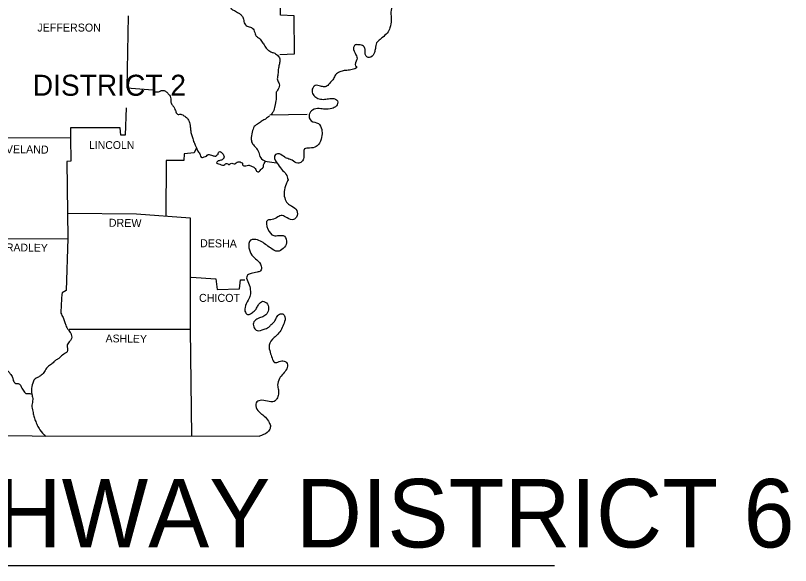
# Model space of a CAD drawing. Extents: x -984 to 3998, y 83 to 2143.
# Drawn here: x 2999.8 to 3407.1, y 1332.5 to 1621.8 of the extents above; entities that cross this region are included whole.
import ezdxf

# ---------------------------------------------------------------- set-up
doc = ezdxf.new("R2010")
doc.units = 0
for name, color, linetype in [('Level 1', 7, 'Continuous'), ('Level 2', 7, 'Continuous'), ('Level 3', 7, 'Continuous')]:
    doc.layers.add(name, color=color, linetype=linetype)

msp = doc.modelspace()

# ---------------------------------------------------------------- linework, layer by layer
at = {"layer": 'Level 1'}
msp.add_line((3133.42, 1569.58), (3152.99, 1569.88), dxfattribs=at)
for points in [[(3138.71, 1601.18), (3146.34, 1601.67), (3146.24, 1621.54), (3139.1, 1622.02), (3139.49, 1660.87), (3133.33, 1661.75), (3133.13, 1687.87), (3216.59, 1688.46)], [(3059.06, 1621.63), (3058.28, 1583.77), (3071.88, 1582.69)], [(3057.99, 1573.3), (3057.4, 1558.92), (3055.15, 1558.92), (3054.76, 1562.73), (3028.73, 1562.73), (3028.73, 1557.25)], [(2993.9, 1557.55), (3028.54, 1557.35)], [(3028.73, 1557.35), (3028.83, 1545.12), (3026.78, 1545.02), (3027.36, 1504.42)], [(3094.87, 1552.17), (3093.7, 1549.52), (3088.51, 1549.04), (3088.22, 1545.51), (3078.93, 1545.51), (3078.83, 1516.26)], [(3027.07, 1517.73), (3063.37, 1517.43), (3091.55, 1515.28)], [(3091.55, 1515.28), (3091.55, 1456.77), (3092.33, 1400.51)], [(2983.14, 1504.32), (3027.36, 1504.42)], [(3027.36, 1504.42), (3026.39, 1477.22), (3024.23, 1475.85)], [(3092.04, 1484.07), (3105.15, 1483.29), (3105.73, 1477.61), (3117.57, 1478), (3118.06, 1482.8), (3120.31, 1482.8)], [(2769.26, 1480.25), (2769.46, 1401.1), (3128.04, 1400.51)], [(3027.95, 1456.87), (3091.55, 1456.87)]]:
    msp.add_lwpolyline(points, dxfattribs=at)
for points in [[(3210.42, 1664.78), (3208.17, 1661.94), (3204.85, 1663.71), (3204.85, 1666.05), (3205.34, 1668.5), (3204.16, 1670.06), (3202.11, 1669.38), (3202.11, 1666.35), (3201.91, 1663.41), (3201.32, 1659.2), (3202.69, 1657.93), (3205.83, 1657.54), (3208.08, 1656.95), (3209.45, 1654.7), (3209.35, 1651.96), (3208.27, 1649.32), (3206.71, 1647.17), (3204.26, 1646.39), (3202.3, 1647.66), (3201.52, 1650.2), (3200.64, 1652.45), (3198.98, 1654.12), (3197.22, 1652.26), (3196.82, 1648.83), (3196.92, 1645.9), (3196.92, 1641.89), (3199.47, 1639.24), (3201.03, 1636.21), (3200.54, 1633.47), (3198.68, 1630.24), (3197.9, 1627.41), (3197.12, 1623.59), (3197.22, 1619.38), (3196.53, 1615.27), (3195.16, 1612.53), (3192.62, 1610.28), (3190.95, 1608.82), (3189.58, 1607.35), (3188.9, 1604.41), (3188.41, 1602.36), (3186.55, 1599.91), (3185.08, 1599.72), (3183.91, 1600.7), (3183.52, 1602.36), (3183.52, 1604.02), (3182.74, 1605.69), (3180.29, 1606.37), (3178.33, 1606.27), (3177.45, 1604.9), (3178.72, 1601.09), (3179.21, 1598.64), (3178.53, 1595.31), (3178.92, 1594.92), (3175.4, 1593.06), (3172.56, 1592.77), (3170.21, 1592.09), (3167.96, 1590.62), (3166.88, 1588.47), (3165.32, 1586.7), (3163.95, 1585.04), (3162.09, 1584.26), (3160.04, 1584.65), (3157.3, 1584.94), (3155.73, 1582.99), (3156.22, 1580.15), (3158.08, 1578.49), (3160.82, 1577.7), (3163.66, 1577.9), (3166.4, 1578.19), (3168.94, 1576.82), (3168.45, 1574.18), (3166, 1572.91), (3162.38, 1572.52), (3159.45, 1572.81), (3155.93, 1572.03), (3154.17, 1569.78), (3155.14, 1566.35), (3158.96, 1564.98), (3160.72, 1561.76), (3160.82, 1558.72), (3159.55, 1554.71), (3157.79, 1552.85), (3154.36, 1552.07), (3151.72, 1551.58), (3151.33, 1547.08), (3150.15, 1544.83), (3148.1, 1544.14), (3145.16, 1545.61), (3143.4, 1546.3), (3141.25, 1547.27), (3138.51, 1548.94), (3136.46, 1548.64), (3137.04, 1544.34), (3137.24, 1544.14), (3139.59, 1540.92), (3141.94, 1538.37), (3143.01, 1535.34)], [(3109.06, 1633.28), (3109.35, 1629.27), (3111.7, 1628.68), (3112.68, 1627.6), (3113.17, 1625.35), (3114.83, 1624.37), (3117.08, 1623), (3118.45, 1622.02), (3119.43, 1620.46), (3120.02, 1617.92), (3121.58, 1616.25), (3123.74, 1615.47), (3125.3, 1613.61), (3126.28, 1610.97), (3127.85, 1609.79), (3129.41, 1607.74), (3130.19, 1606.86), (3131.56, 1604.51), (3132.93, 1603.34), (3133.91, 1602.65), (3135.48, 1602.16), (3137.43, 1600.89), (3138.71, 1598.93), (3138.71, 1597.47), (3138.22, 1595.22), (3137.83, 1592.87), (3137.63, 1590.23), (3137.43, 1587.88), (3138.32, 1585.92), (3137.83, 1582.99), (3136.85, 1581.42), (3136.75, 1579.27), (3136.46, 1576.04), (3136.07, 1574.18), (3135.18, 1571.15), (3133.91, 1569.58)], [(3071.88, 1582.69), (3073.35, 1581.71), (3075.4, 1581.81), (3076.77, 1582.4), (3077.85, 1582.3), (3079.32, 1581.42), (3080.3, 1580.25), (3080.98, 1579.37), (3081.47, 1578), (3081.47, 1576.72), (3081.96, 1574.96), (3082.55, 1574.28), (3083.33, 1573.01), (3083.82, 1571.83), (3084.11, 1571.05), (3085.19, 1569.78), (3086.17, 1569.88), (3087.05, 1569.78), (3088.22, 1569.09), (3089.98, 1567.72), (3090.28, 1567.33), (3091.45, 1564.79), (3091.65, 1563.22), (3091.84, 1561.17), (3092.23, 1559.21), (3093.02, 1557.06), (3093.41, 1555.59), (3094.29, 1553.54), (3094.87, 1552.17), (3095.66, 1550.41), (3096.83, 1548.45), (3097.32, 1547.27), (3098.98, 1547.37), (3100.16, 1547.86), (3101.04, 1548.64), (3102.11, 1548.55), (3103.29, 1548.16), (3104.85, 1547.86), (3105.83, 1548.45), (3106.32, 1548.84), (3106.42, 1549.72), (3107.3, 1550.21), (3108.28, 1549.52), (3109.35, 1547.96), (3109.35, 1546.98), (3108.96, 1546.39), (3107.69, 1545.61), (3105.93, 1545.02), (3105.44, 1544.34), (3107.1, 1543.56), (3109.75, 1543.36), (3110.43, 1543.95), (3112.19, 1543.46), (3112.88, 1543.95), (3115.23, 1543.85), (3116.3, 1544.63), (3118.45, 1544.54), (3119.14, 1544.05), (3119.14, 1543.17), (3120.9, 1542.77), (3122.17, 1543.07), (3123.84, 1542.58), (3125.3, 1541.8), (3126.09, 1540.72), (3127.06, 1539.55), (3127.94, 1539.84), (3128.63, 1540.72), (3130.1, 1542.28), (3130.1, 1543.26), (3130.49, 1543.95), (3130.98, 1544.93)], [(3133.23, 1569), (3131.17, 1567.33), (3129.41, 1566.35), (3127.55, 1564.98), (3125.3, 1563.32), (3124.23, 1560.48), (3123.64, 1556.57), (3124.42, 1554.22), (3126.18, 1552.17), (3127.36, 1550.5), (3128.24, 1547.57), (3130.39, 1545.51), (3131.08, 1545.22)], [(3143.01, 1535.34), (3142.03, 1533.09), (3140.96, 1529.17), (3141.25, 1525.85), (3142.72, 1523.01), (3145.07, 1521.44), (3147.61, 1519.19), (3147.41, 1515.77), (3145.95, 1514.5), (3142.52, 1515.38), (3139.88, 1516.55), (3137.63, 1515.87), (3134.6, 1514.4), (3132.35, 1514.11), (3132.45, 1509.41), (3135.48, 1506.08), (3138.12, 1506.08), (3141.15, 1505.69), (3142.23, 1502.17), (3140.47, 1499.23), (3137.53, 1497.77), (3133.81, 1499.53), (3131.17, 1501.39), (3128.53, 1503.15), (3125.2, 1504.03), (3123.35, 1503.64), (3122.47, 1499.53), (3124.03, 1495.81), (3126.57, 1493.27), (3128.92, 1489.94), (3128.53, 1487.49), (3126.77, 1486.81), (3123.64, 1486.12), (3121.78, 1485.15), (3121.29, 1484.36), (3122.27, 1481.04), (3123.15, 1477.42), (3123.15, 1474.68), (3122.07, 1472.13), (3120.41, 1468.22), (3120.61, 1465.68), (3121.78, 1464.5), (3123.25, 1464.89), (3125.2, 1466.26), (3126.48, 1467.83), (3127.55, 1469.78), (3129.61, 1471.45), (3132.15, 1469.98), (3132.74, 1466.95), (3131.27, 1464.31), (3129.22, 1463.13), (3126.67, 1462.15), (3124.81, 1460), (3125.3, 1457.46), (3126.77, 1456.09), (3130.39, 1456.77), (3132.84, 1457.85), (3134.21, 1459.22), (3135.87, 1460.88), (3136.75, 1462.54), (3138.02, 1464.31), (3140.27, 1464.79), (3141.35, 1463.33), (3140.96, 1460), (3139.59, 1456.87), (3137.73, 1454.23), (3135.67, 1452.37), (3133.13, 1448.36), (3133.62, 1444.64), (3134.6, 1441.61), (3135.97, 1439.26), (3138.32, 1439.75), (3140.96, 1440.04), (3142.52, 1438.77), (3142.33, 1436.03), (3140.37, 1433.39), (3138.51, 1430.84), (3137.53, 1427.32), (3137.92, 1424.88), (3137.92, 1422.63), (3137.14, 1420.18), (3135.77, 1418.81), (3132.15, 1418.91), (3128.34, 1419.3), (3126.28, 1418.12), (3126.67, 1414.8), (3128.92, 1412.35), (3130.49, 1411.08), (3132.74, 1408.34), (3133.72, 1406.09), (3133.42, 1404.13), (3132.05, 1402.47), (3128.04, 1400.51)], [(3024.23, 1475.85), (3023.94, 1472.82), (3023.84, 1469.98), (3023.65, 1467.24), (3023.65, 1465.19), (3024.82, 1462.94), (3025.51, 1460.78), (3026.19, 1458.92), (3027.56, 1456.48), (3028.83, 1454.62), (3029.22, 1451.98), (3028.44, 1450.61), (3026.97, 1448.55), (3026.87, 1444.84), (3025.11, 1443.66), (3022.86, 1441.7), (3021.59, 1440.82), (3020.22, 1439.94), (3018.75, 1438.38), (3016.6, 1436.91), (3015.04, 1434.46), (3013.28, 1432.61), (3011.81, 1431.63), (3009.75, 1430.36), (3008.87, 1428.4), (3008.19, 1424.78), (3008.48, 1422.14), (3008.87, 1419.79), (3008.38, 1416.85), (3008.87, 1413.62), (3009.36, 1411.08), (3010.14, 1408.83), (3011.22, 1406.29), (3012.59, 1403.94), (3015.53, 1400.32)], [(2926.69, 1453.25), (2928.25, 1454.33), (2929.72, 1454.91), (2931.19, 1454.62), (2932.75, 1454.42), (2934.12, 1454.62), (2935.88, 1454.33), (2937.35, 1453.45), (2939.01, 1452.76), (2940.68, 1452.76), (2942.14, 1452.76), (2943.42, 1451.88), (2945.77, 1451.98), (2947.72, 1452.76), (2949.68, 1453.35), (2952.32, 1453.64), (2954.67, 1451.98), (2956.33, 1450.61), (2957.7, 1449.04), (2958.68, 1447.28), (2959.76, 1446.3), (2961.52, 1445.62), (2962.89, 1445.32), (2964.55, 1444.84), (2965.43, 1444.44), (2966.21, 1442.59), (2967.49, 1440.04), (2969.93, 1439.16), (2972.96, 1440.33), (2975.41, 1441.02), (2977.17, 1441.61), (2978.25, 1442), (2979.23, 1442.1), (2978.93, 1442.29), (2980.11, 1442.59), (2981.18, 1441.8), (2981.87, 1440.73), (2983.04, 1439.16), (2984.12, 1437.79), (2985.19, 1437.3), (2986.27, 1437.89), (2987.74, 1437.4), (2989.01, 1436.91), (2990.48, 1436.52), (2991.75, 1436.42), (2993.41, 1436.03), (2994.69, 1435.34), (2995.86, 1434.66), (2997.03, 1433.39), (2998.21, 1431.43), (2998.6, 1429.87), (2999.97, 1428.3), (3001.24, 1428.3), (3003.1, 1425.76), (3003.78, 1424.78), (3005.25, 1423.02), (3006.33, 1423.02), (3008.38, 1422.63)]]:
    msp.add_spline(points, degree=3, dxfattribs=at)
at = {"layer": 'Level 2'}
msp.add_line((2628.58, 1332.51), (3283.1, 1332.51), dxfattribs=at)
at = {"layer": 'Level 3'}
msp.add_line((3130.78, 1545.12), (3136.95, 1544.34), dxfattribs=at)

# ---------------------------------------------------------------- texts
at = {"layer": 'Level 2'}
for s, height, p in [('JEFFERSON', 4.207, (3011.22, 1613.32)), ('LINCOLN', 4.109, (3038.42, 1551.58)), ('CHICOT', 4.207, (3096.24, 1471.15)), ('ARKANSAS HIGHWAY DISTRICT 6', 36, (2628.15, 1342.01))]:
    msp.add_text(s, height=height, dxfattribs=at).set_placement(p)
for s, height, rotation, p in [('CLEVELAND', 4.207, 359.3377, (2983.73, 1549.52)), ('DREW', 4.206, 359.2258, (3048.79, 1510.68)), ('DESHA', 4.206, 359.3704, (3096.73, 1499.92)), ('BRADLEY', 4.108, 359.1449, (2991.07, 1497.87)), ('ASHLEY', 4.109, 359.2361, (3047.13, 1449.92))]:
    msp.add_text(s, height=height, rotation=rotation, dxfattribs=at).set_placement(p)
at = {"layer": 'Level 3'}
msp.add_text('DISTRICT 2', height=11.056, dxfattribs=at).set_placement((3008.87, 1579.56))

doc.saveas('drawing.dxf')
